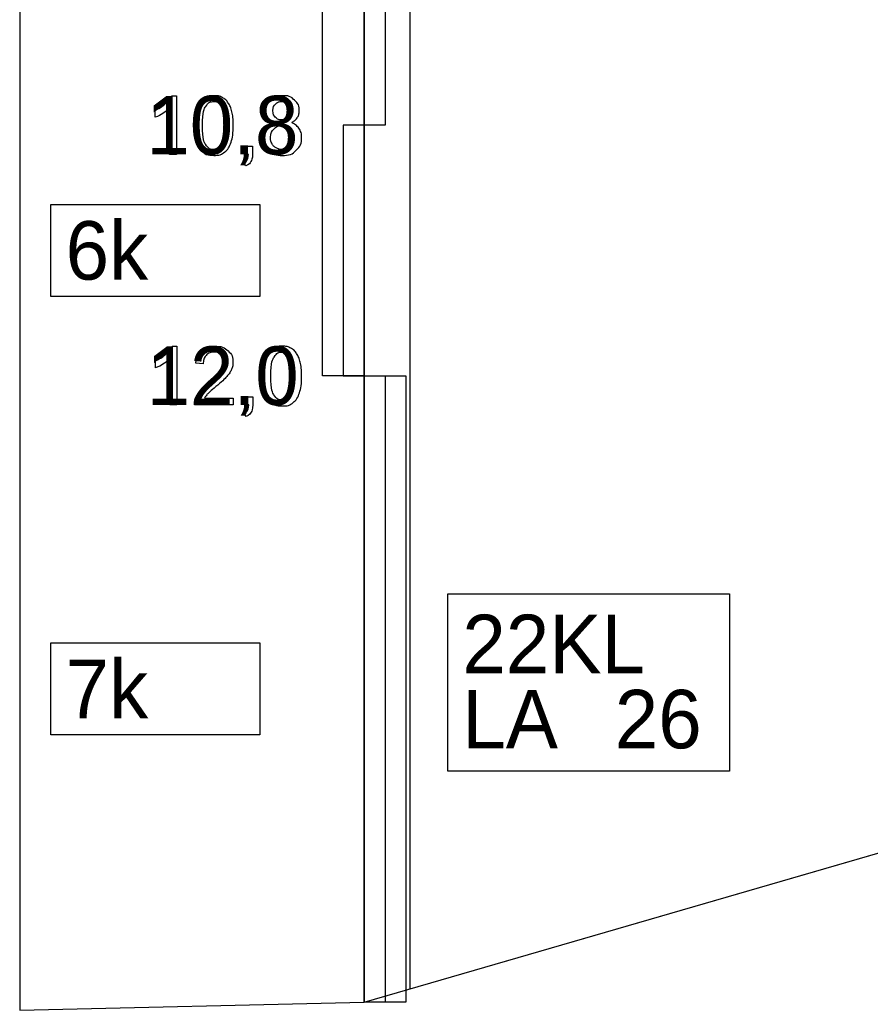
# Model space of a CAD drawing. Extents: x 532503 to 539665, y 6557663 to 6561526.
# Drawn here: x 537081.8 to 537163.3, y 6560005.9 to 6560100.8 of the extents above; entities that cross this region are included whole.
import ezdxf

# ---------------------------------------------------------------- set-up
doc = ezdxf.new("R2010")
doc.units = 0
for name, color, linetype in [('GEOLPUNKT', 7, 'Continuous'), ('Kaitsevöönd', 7, 'Continuous'), ('Plokid', 7, 'Continuous'), ('Proovid', 7, 'Continuous'), ('Täide', 7, 'Continuous')]:
    doc.layers.add(name, color=color, linetype=linetype)

msp = doc.modelspace()

# ---------------------------------------------------------------- linework, layer by layer
at = {"layer": 'GEOLPUNKT'}
msp.add_line((537114.818, 6560306.67), (537114.818, 6560006.67), dxfattribs=at)
at = {"layer": 'Kaitsevöönd'}
msp.add_lwpolyline([(537081.832, 6560005.9), (537114.818, 6560006.67), (537183.93, 6560026.727), (537280.034, 6560100.213), (537353.475, 6560157.724), (537409.981, 6560181.67), (537680.404, 6560181.07), (537927.278, 6560223.47), (538157.309, 6560221.07), (538426.576, 6560200.27), (538783.9, 6560154.27), (538809.139, 6560154.375)], dxfattribs=at)
at = {"layer": 'Plokid'}
msp.add_line((537119.211, 6560007.945), (537119.211, 6560197.372), dxfattribs=at)
at = {"layer": 'Proovid'}
for points in [[(537110.818, 6560170.67), (537114.818, 6560170.67), (537114.818, 6560066.67), (537110.818, 6560066.67)], [(537114.818, 6560130.67), (537116.818, 6560130.67), (537116.818, 6560090.67), (537114.818, 6560090.67)], [(537114.818, 6560090.67), (537112.818, 6560090.67), (537112.818, 6560066.67), (537114.818, 6560066.67)], [(537084.818, 6560083.07), (537104.818, 6560083.07), (537104.818, 6560074.27), (537084.818, 6560074.27)], [(537114.818, 6560066.67), (537116.818, 6560066.67), (537116.818, 6560006.67), (537114.818, 6560006.67)], [(537114.818, 6560066.67), (537118.818, 6560066.67), (537118.818, 6560006.67), (537114.818, 6560006.67)], [(537122.818, 6560045.78), (537149.818, 6560045.78), (537149.818, 6560028.78), (537122.818, 6560028.78)], [(537084.818, 6560041.07), (537104.818, 6560041.07), (537104.818, 6560032.27), (537084.818, 6560032.27)]]:
    msp.add_lwpolyline(points, close=True, dxfattribs=at)
for points in [[(537096.411, 6560093.492), (537096.854, 6560093.492), (537096.854, 6560087.87)], [(537094.793, 6560091.422), (537094.793, 6560092.086)], [(537096.854, 6560087.87), (537096.167, 6560087.87), (537096.167, 6560092.25)], [(537103.338, 6560087.87), (537103.338, 6560088.651), (537104.119, 6560088.651), (537104.119, 6560087.87)], [(537103.726, 6560087.87), (537103.338, 6560087.87)], [(537103.483, 6560086.76), (537103.291, 6560087.055)], [(537096.441, 6560069.492), (537096.884, 6560069.492), (537096.884, 6560063.87)], [(537094.823, 6560067.422), (537094.823, 6560068.086)], [(537096.884, 6560063.87), (537096.197, 6560063.87), (537096.197, 6560068.25)], [(537099.394, 6560067.801), (537098.685, 6560067.874)], [(537103.368, 6560063.87), (537103.368, 6560064.651), (537104.149, 6560064.651), (537104.149, 6560063.87)], [(537102.258, 6560064.532), (537102.258, 6560063.87), (537098.557, 6560063.87)], [(537099.513, 6560064.532), (537102.258, 6560064.532)], [(537103.756, 6560063.87), (537103.368, 6560063.87)], [(537103.513, 6560062.76), (537103.321, 6560063.055)]]:
    msp.add_lwpolyline(points, dxfattribs=at)
for points in [[(537094.793, 6560092.086), (537095.369, 6560092.357), (537095.801, 6560092.743), (537096.232, 6560093.129), (537096.411, 6560093.492)], [(537098.617, 6560090.632), (537098.617, 6560091.625), (537098.821, 6560092.231), (537099.026, 6560092.837), (537099.428, 6560093.164), (537099.831, 6560093.492), (537100.442, 6560093.492), (537100.892, 6560093.492), (537101.233, 6560093.31), (537101.574, 6560093.129), (537101.794, 6560092.787), (537102.014, 6560092.446), (537102.14, 6560091.955), (537102.266, 6560091.464), (537102.266, 6560090.632), (537102.266, 6560089.647), (537102.064, 6560089.041), (537101.862, 6560088.435), (537101.459, 6560088.105), (537101.056, 6560087.776), (537100.442, 6560087.776), (537099.632, 6560087.776), (537099.171, 6560088.354), (537098.617, 6560089.055), (537098.617, 6560090.632)], [(537106.202, 6560090.909), (537105.772, 6560091.066), (537105.564, 6560091.356), (537105.357, 6560091.646), (537105.357, 6560092.05), (537105.357, 6560092.66), (537105.795, 6560093.076), (537106.234, 6560093.492), (537106.963, 6560093.492), (537107.695, 6560093.492), (537108.141, 6560093.066), (537108.588, 6560092.641), (537108.588, 6560092.031), (537108.588, 6560091.642), (537108.383, 6560091.354), (537108.179, 6560091.066), (537107.762, 6560090.909), (537108.278, 6560090.741), (537108.548, 6560090.367), (537108.818, 6560089.992), (537108.818, 6560089.473), (537108.818, 6560088.754), (537108.311, 6560088.265), (537107.803, 6560087.776), (537106.974, 6560087.776), (537106.146, 6560087.776), (537105.638, 6560088.267), (537105.13, 6560088.758), (537105.13, 6560089.492), (537105.13, 6560090.038), (537105.409, 6560090.407), (537105.687, 6560090.776), (537106.202, 6560090.909)], [(537096.167, 6560092.25), (537095.919, 6560092.014), (537095.516, 6560091.777), (537095.113, 6560091.54), (537094.793, 6560091.422)], [(537099.326, 6560090.632), (537099.326, 6560089.251), (537099.647, 6560088.795), (537099.969, 6560088.34), (537100.442, 6560088.34), (537100.914, 6560088.34), (537101.236, 6560088.797), (537101.558, 6560089.254), (537101.558, 6560090.632), (537101.558, 6560092.015), (537101.237, 6560092.469), (537100.915, 6560092.924), (537100.434, 6560092.924), (537099.962, 6560092.924), (537099.679, 6560092.523), (537099.326, 6560092.011), (537099.326, 6560090.632)], [(537106.065, 6560092.074), (537106.065, 6560091.677), (537106.318, 6560091.426), (537106.572, 6560091.174), (537106.98, 6560091.174), (537107.377, 6560091.174), (537107.628, 6560091.424), (537107.879, 6560091.673), (537107.879, 6560092.036), (537107.879, 6560092.413), (537107.62, 6560092.671), (537107.361, 6560092.928), (537106.972, 6560092.928), (537106.579, 6560092.928), (537106.322, 6560092.676), (537106.065, 6560092.425), (537106.065, 6560092.074)], [(537105.839, 6560089.487), (537105.839, 6560089.192), (537105.977, 6560088.917), (537106.115, 6560088.642), (537106.389, 6560088.491), (537106.664, 6560088.34), (537106.98, 6560088.34), (537107.473, 6560088.34), (537107.791, 6560088.657), (537108.11, 6560088.974), (537108.11, 6560089.464), (537108.11, 6560089.961), (537107.782, 6560090.286), (537107.454, 6560090.61), (537106.957, 6560090.61), (537106.472, 6560090.61), (537106.156, 6560090.289), (537105.839, 6560089.968), (537105.839, 6560089.487)], [(537103.291, 6560087.055), (537103.509, 6560087.151), (537103.612, 6560087.336), (537103.715, 6560087.522), (537103.726, 6560087.87)], [(537104.119, 6560087.87), (537104.119, 6560087.438), (537103.967, 6560087.172), (537103.814, 6560086.906), (537103.483, 6560086.76)], [(537094.823, 6560068.086), (537095.399, 6560068.357), (537095.83, 6560068.743), (537096.262, 6560069.129), (537096.441, 6560069.492)], [(537098.685, 6560067.874), (537098.758, 6560068.664), (537099.232, 6560069.078), (537099.705, 6560069.492), (537100.504, 6560069.492), (537101.31, 6560069.492), (537101.78, 6560069.045), (537102.249, 6560068.598), (537102.249, 6560067.938), (537102.249, 6560067.602), (537102.112, 6560067.277), (537101.975, 6560066.953), (537101.656, 6560066.594), (537101.338, 6560066.235), (537100.598, 6560065.609), (537099.979, 6560065.089), (537099.803, 6560064.904), (537099.628, 6560064.719), (537099.513, 6560064.532)], [(537105.169, 6560066.632), (537105.169, 6560067.625), (537105.373, 6560068.231), (537105.577, 6560068.837), (537105.98, 6560069.164), (537106.383, 6560069.492), (537106.994, 6560069.492), (537107.444, 6560069.492), (537107.785, 6560069.31), (537108.126, 6560069.129), (537108.346, 6560068.787), (537108.566, 6560068.446), (537108.692, 6560067.955), (537108.818, 6560067.464), (537108.818, 6560066.632), (537108.818, 6560065.647), (537108.616, 6560065.041), (537108.414, 6560064.435), (537108.011, 6560064.105), (537107.608, 6560063.776), (537106.994, 6560063.776), (537106.184, 6560063.776), (537105.722, 6560064.354), (537105.169, 6560065.055), (537105.169, 6560066.632)], [(537098.557, 6560063.87), (537098.55, 6560064.119), (537098.638, 6560064.348), (537098.779, 6560064.727), (537099.091, 6560065.093), (537099.402, 6560065.46), (537099.99, 6560065.94), (537100.901, 6560066.69), (537101.221, 6560067.127), (537101.541, 6560067.564), (537101.541, 6560067.954), (537101.541, 6560068.363), (537101.249, 6560068.643), (537100.957, 6560068.924), (537100.488, 6560068.924), (537099.993, 6560068.924), (537099.695, 6560068.626), (537099.398, 6560068.328), (537099.394, 6560067.801)], [(537105.877, 6560066.632), (537105.877, 6560065.251), (537106.199, 6560064.795), (537106.521, 6560064.34), (537106.994, 6560064.34), (537107.466, 6560064.34), (537107.788, 6560064.797), (537108.11, 6560065.254), (537108.11, 6560066.632), (537108.11, 6560068.015), (537107.788, 6560068.469), (537107.467, 6560068.924), (537106.986, 6560068.924), (537106.514, 6560068.924), (537106.231, 6560068.523), (537105.877, 6560068.011), (537105.877, 6560066.632)], [(537096.197, 6560068.25), (537095.949, 6560068.014), (537095.546, 6560067.777), (537095.143, 6560067.54), (537094.823, 6560067.422)], [(537103.321, 6560063.055), (537103.539, 6560063.151), (537103.642, 6560063.336), (537103.745, 6560063.522), (537103.756, 6560063.87)], [(537104.149, 6560063.87), (537104.149, 6560063.438), (537103.996, 6560063.172), (537103.844, 6560062.906), (537103.513, 6560062.76)]]:
    msp.add_open_spline(points, degree=3, dxfattribs=at)
at = {"layer": 'Täide'}
for points in [[(537081.832, 6560303.038), (537081.832, 6560171.87), (537081.832, 6560005.9)], [(537081.832, 6560276.692), (537081.832, 6560171.87), (537081.832, 6560005.9)], [(537081.832, 6560265.362), (537081.832, 6560171.87), (537081.832, 6560005.9)], [(537081.832, 6560005.9), (537114.818, 6560006.67), (537183.93, 6560026.727), (537280.034, 6560100.213), (537353.475, 6560157.724), (537409.981, 6560181.67), (537680.404, 6560181.07)], [(537081.832, 6560005.9), (537114.818, 6560006.67), (537183.93, 6560026.727), (537280.034, 6560100.213), (537305.831, 6560120.415)]]:
    msp.add_lwpolyline(points, dxfattribs=at)

# ---------------------------------------------------------------- texts
at = {"layer": 'Proovid'}
for s, p in [('10,8', (537093.943, 6560087.87)), ('6k', (537086.218, 6560075.87)), ('12,0', (537093.973, 6560063.87)), ('22KL', (537124.218, 6560038.18)), ('7k', (537086.218, 6560033.87)), ('LA', (537124.218, 6560030.98)), ('26', (537138.818, 6560030.98))]:
    msp.add_text(s, height=5.6, dxfattribs=at).set_placement(p)

doc.saveas('drawing.dxf')
